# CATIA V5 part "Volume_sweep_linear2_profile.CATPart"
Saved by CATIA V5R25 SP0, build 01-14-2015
Part number: Part1
Bounding box of the stored display mesh (mm): x -59.804 to 154.398, y 1.869 to 39.866, z 0 to 157
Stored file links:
  E:\cadcim\GSD_cat_v5-6r2014\Part_files\Volume_sweep_linear2_profile.CATPart
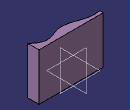
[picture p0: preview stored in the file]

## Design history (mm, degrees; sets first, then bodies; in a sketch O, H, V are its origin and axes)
Set1
  Sketch1 on xy-plane, origin (0, 0, 0), H (1, 0, 0), V (0, 1, 0)
    spline S1 through (154.3979, 1.8689) (93.1563, 21.7077) (57.7914, 10.782) (13.5134, 17.6824) (-59.804, 28.3207)
  Extrude1: Lim1 157, Lim2 0, Element1 Sketch1
  Sweep1: type Segment, GuideCrv Extrude1, Length1 10, Length2 0, Angle 0, DraftDirection zx-plane
Body1 (main body)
